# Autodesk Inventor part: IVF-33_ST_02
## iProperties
Created: 2008-10
Part Number: IVF-33_ST_02
Material: 3.3206  AlMgSi 0.5  H22
Document SubType Name: Blech
Designer: Gawin
Density: 2.66 g/cm^3
Mass: 50.9863 g
Surface Area: 195.825 cm^2
Volume: 19.1678 cm^3
Stock Number: IVF-33_ST_02
Author: Gawin
